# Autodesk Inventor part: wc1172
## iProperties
Shininess: 64.0
Length Units: 11272
Angle Units: 11279
Time Units: 11290
Mass Units: 11286
Length Display Precision: 3
Angle Display Precision: 2
Compacted: True
Part Number: wc1172
Document SubType Name: Modeling
Created: 2004-08
Designer: John Blackburn
Manufacturer: Standard
Standards Organization: Custom
Material: Phenolic
Density: 0.0
Volumn: 0.0
Area: 0.0
PropertySet Name: Model Information
Control State: 0
Master: False
Checked Out: False
Author: John Blackburn
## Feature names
1. Base1
